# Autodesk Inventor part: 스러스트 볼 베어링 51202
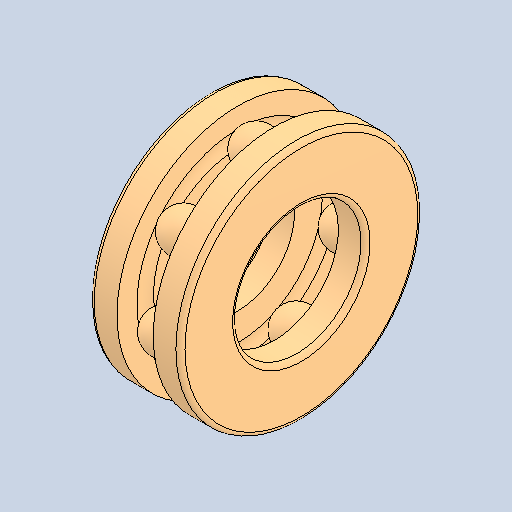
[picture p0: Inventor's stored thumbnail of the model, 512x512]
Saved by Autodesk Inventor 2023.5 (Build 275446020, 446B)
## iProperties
Created: 2026-07
Part Number: 스러스트 볼 베어링 51202
Material: 강철, 연강
Description: 롤링 베어링 - 플랫 뒷면이 있는 스러스트 볼 베어링
Document SubType Name: Modeling
Designer: 1강의실14
Density: 7.85 g/cm^3
Appearance: 기본값
Author: jhkim
Sending System: Autodesk Inventor 2027
Preprocessor: ST-DEVELOPER v20.1
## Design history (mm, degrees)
node "스러스트 볼 베어링 512021"
node "솔리드1"
node "솔리드2"
node "솔리드3"
node "솔리드4"
node "솔리드5"
node "솔리드6"
node "솔리드7"
node "솔리드8"
node "솔리드9"
body "Solid1"
node "Solid1:1"
node "Solid1:2"
node "Solid1:3"
node "Solid1:4"
node "Solid1:5"
node "Solid1:6"
node "Solid1:7"
node "Solid1:8"
